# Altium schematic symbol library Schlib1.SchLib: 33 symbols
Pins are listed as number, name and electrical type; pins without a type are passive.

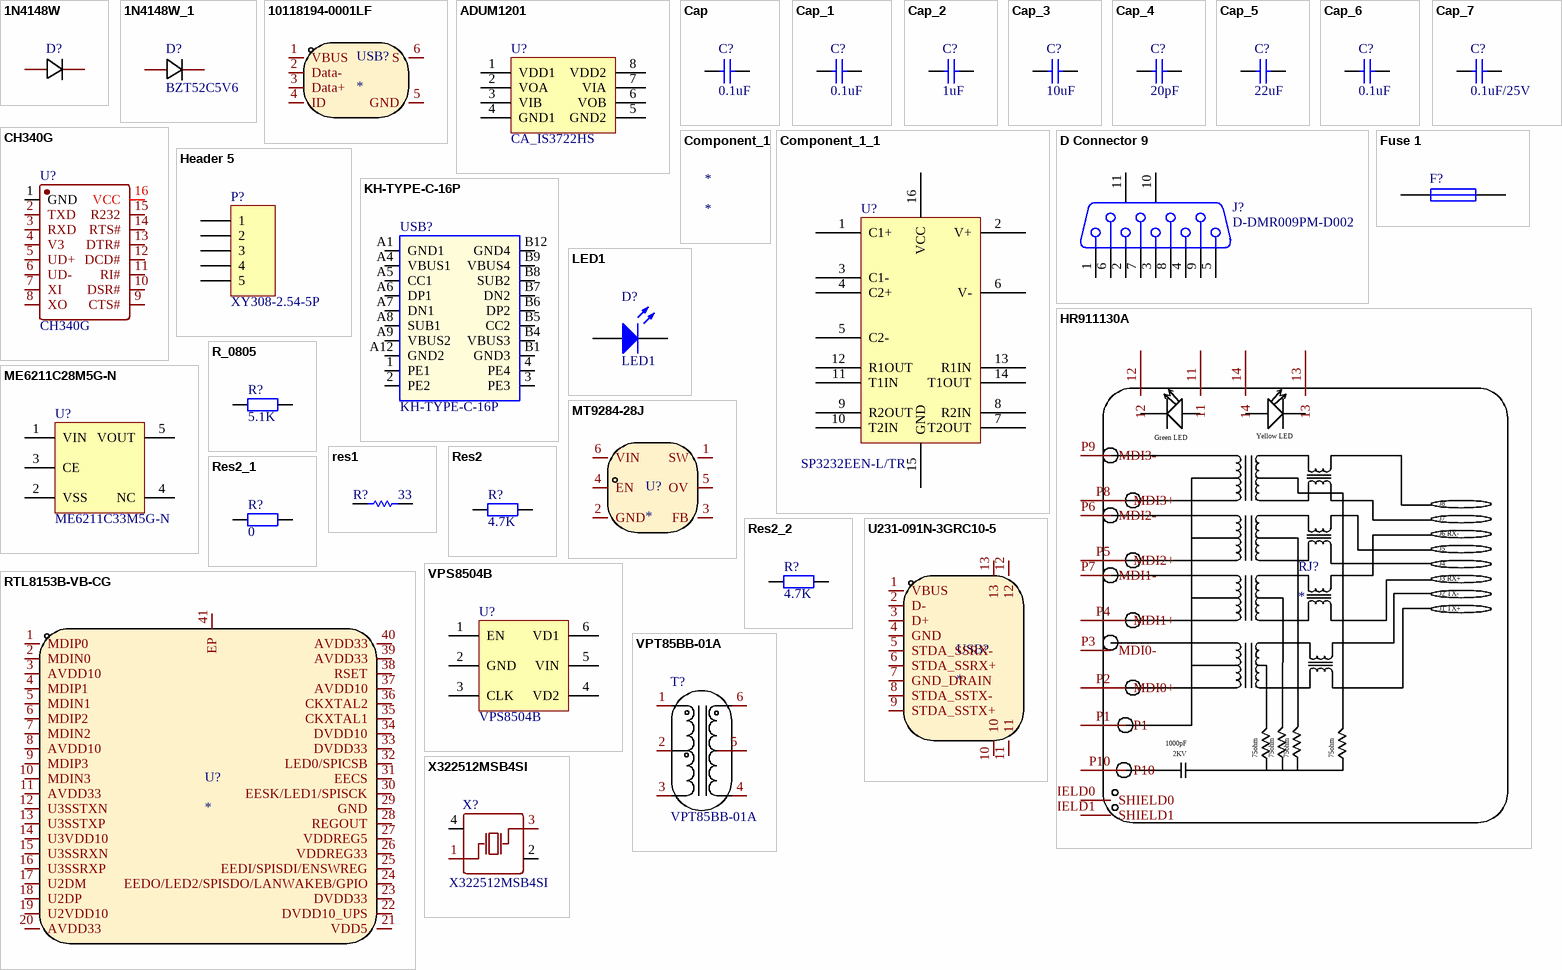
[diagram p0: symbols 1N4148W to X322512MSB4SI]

## 1N4148W
designator D?, comment B5819W SL  (value not drawn)
footprint SOD-123
pins: 1 C, 2 A

## 1N4148W_1
designator D?, comment BZT52C5V6
footprint SOD-123
pins: 1 C, 2 A

## 10118194-0001LF
designator USB?
pins: 1 VBUS, 2 Data-, 3 Data+, 4 ID, 5 GND, 6 S

## ADUM1201
designator U?, comment CA_IS3722HS
footprint SOP8
footprint SOP-8_150mil
pins: 1 VDD1, 2 VOA, 3 VIB, 4 GND1, 5 GND2, 6 VOB, 7 VIA, 8 VDD2

## Cap
designator C?, comment 0.1uF
贴片电容
footprint RAD-0.3 (Radial Cap, Thru-Hole; 2 Leads; 0.3 in Pin Spacing)
simulation model CAP (Capacitor)
signal-integrity model Cap
footprint 0805-C
footprint 0603-C
pins: 1, 2

## Cap_1
designator C?, comment 0.1uF
贴片电容
simulation model CAP (Capacitor)
signal-integrity model Cap
footprint 0603-C
pins: 1, 2

## Cap_2
designator C?, comment 1uF
贴片电容; Value: 0.1uF
footprint RAD-0.3 (Radial Cap, Thru-Hole; 2 Leads; 0.3 in Pin Spacing)
simulation model CAP (Capacitor)
signal-integrity model Cap
footprint 0805-C
footprint 0603-C
pins: 1, 2

## Cap_3
designator C?, comment 10uF
贴片电容; Value: 0.1uF
footprint RAD-0.3 (Radial Cap, Thru-Hole; 2 Leads; 0.3 in Pin Spacing)
simulation model CAP (Capacitor)
signal-integrity model Cap
footprint 0805-C
footprint 0603-C
footprint 0805-C
pins: 1, 2

## Cap_4
designator C?, comment 20pF
贴片电容
simulation model CAP (Capacitor)
signal-integrity model Cap
footprint 0603-C
pins: 1, 2

## Cap_5
designator C?, comment 22uF
贴片电容
simulation model CAP (Capacitor)
signal-integrity model Cap
footprint 0603-C
footprint 0805-C
pins: 1, 2

## Cap_6
designator C?, comment 0.1uF
Capacitor; Value: 100pF
footprint 0603C
footprint 0603-C
pins: 1, 2

## Cap_7
designator C?, comment 0.1uF/25V
贴片电容
simulation model CAP (Capacitor)
signal-integrity model Cap
footprint 0603-C
pins: 1, 2

## CH340G
designator U?
footprint SOP-16
pins: 1 GND, 2 TXD, 3 RXD, 4 V3, 5 UD+, 6 UD-, 7 XI, 8 XO, 9 CTS#, 10 DSR#, 11 RI#, 12 DCD#, 13 DTR#, 14 RTS#, 15 R232, 16 VCC

## Component_1
designator *

## Component_1_1
designator U?, comment SP3232EEN-L/TR
RS232电平转换芯片
footprint SOIC127P600-16L
pins: 1 C1+, 2 V+, 3 C1-, 4 C2+, 5 C2-, 6 V-, 7 T2OUT, 8 R2IN, 9 R2OUT, 10 T2IN, 11 T1IN, 12 R1OUT, 13 R1IN, 14 T1OUT, 15 GND, 16 VCC

## D Connector 9
designator J?, comment D-DMR009PM-D002
DB9连接器 母头; PackageDocument: O; Positions: 9; Gender: Receptacle
footprint DSUB1.385-2H9 (Connector; D Subminiature; 9 Position; Right Angle; Pitch 1.385 mm)
signal-integrity model Connector
pins: 1, 2, 3, 4, 5, 6, 7, 8, 9, 10 MH1, 11 MH2

## Fuse 1
designator F?, comment BSMD0805-050-24V  (value not drawn)
footprint PIN-W2/E2.8 (Thru-Hole; 2 Leads)
simulation model FUSE (Spice Subcircuit)
footprint 1206-F
footprint 0805-L
pins: 1, 2

## Header 5
designator P?, comment XY308-2.54-5P
Header, 5-Pin
footprint HDR1X5 (Connector; Header; 5 Position)
signal-integrity model Connector
footprint CONN-TH_XY308-2.54-5P (2.54接线端子)
footprint Model Name (Footprint not found)
footprint CONN-TH_5P-P3.81_KF124-3.81-5P (3.81 5P接线端子)
pins: 1, 2, 3, 4, 5

## HR911130A
designator RJ?
pins: 11, 12, 13, 14, P1, P2 MDI0+, P3 MDI0-, P4 MDI1+, P5 MDI2+, P6 MDI2-, P7 MDI1-, P8 MDI3+, P9 MDI3-, P10, SHIELD0, SHIELD1

## KH-TYPE-C-16P
designator USB?
Type-C
footprint USB-C-SMD_KH-TYPE-C-16P
pins: 1 PE1, 2 PE2, 3 PE3, 4 PE4, A1 GND1, A4 VBUS1, A5 CC1, A6 DP1, A7 DN1, A8 SUB1, A9 VBUS2, A12 GND2, B1 GND3, B4 VBUS3, B5 CC2, B6 DP2, B7 DN2, B8 SUB2, B9 VBUS4, B12 GND4

## LED1
designator D?
LED-绿
footprint LED-1 (LED; 2 Leads)
simulation model LED1 (Diode)
footprint 0805-LED
footprint 0603-LED
footprint LED-TH_BD3.0-P2.54
pins: 1 A, 2 K

## ME6211C28M5G-N
designator U?, comment ME6211C33M5G-N
LDO-2.8V
footprint SOT-23-5
pins: 1 VIN, 2 VSS, 3 CE, 4 NC, 5 VOUT

## MT9284-28J
designator U?
pins: 1 SW, 2 GND, 3 FB, 4 EN, 5 OV, 6 VIN

## R_0805
designator R?, comment 5.1K
电阻
footprint 0603- R
pins: 1, 2

## res1
designator R?, comment 33
Resistor; Value: 1K
simulation model RESISTOR (Resistor)
signal-integrity model Res
footprint R0603
footprint 0603- R
pins: 1, 2
1 alternate drawing of the same symbol

## Res2
designator R?, comment 4.7K
贴片电阻
footprint AXIAL-0.4 (Axial Device, Thru-Hole; 2 Leads; 0.4 in Pin Spacing)
simulation model RESISTOR (Resistor)
signal-integrity model Res
footprint 0805-R
footprint 0603- R
pins: 1, 2

## Res2_1
designator R?, comment 0
贴片电阻
simulation model RESISTOR (Resistor)
signal-integrity model Res
footprint 0603- R
pins: 1, 2

## Res2_2
designator R?, comment 4.7K
贴片电阻
simulation model RESISTOR (Resistor)
signal-integrity model Res
footprint 0603- R
pins: 1, 2

## RTL8153B-VB-CG
designator U?
footprint QFN-40-EP(5x5)
pins: 1 MDIP0, 2 MDIN0, 3 AVDD10, 4 MDIP1, 5 MDIN1, 6 MDIP2, 7 MDIN2, 8 AVDD10, 9 MDIP3, 10 MDIN3, 11 AVDD33, 12 U3SSTXN, 13 U3SSTXP, 14 U3VDD10, 15 U3SSRXN, 16 U3SSRXP, 17 U2DM, 18 U2DP, 19 U2VDD10, 20 AVDD33, 21 VDD5, 22 DVDD10_UPS, 23 DVDD33, 24 EEDO/LED2/SPISDO/LANWAKEB/GPIO, 25 EEDI/SPISDI/ENSWREG, 26 VDDREG33, 27 VDDREG5, 28 REGOUT, 29 GND, 30 EESK/LED1/SPISCK, 31 EECS, 32 LED0/SPICSB, 33 DVDD33, 34 DVDD10, 35 CKXTAL1, 36 CKXTAL2, 37 AVDD10, 38 RSET, 39 AVDD33, 40 AVDD33, 41 EP

## U231-091N-3GRC10-5
designator USB?
USB3.0
footprint USB-A-TH_U231-091N-5
pins: 1 VBUS, 2 D-, 3 D+, 4 GND, 5 STDA_SSRX-, 6 STDA_SSRX+, 7 GND_DRAIN, 8 STDA_SSTX-, 9 STDA_SSTX+, 10, 11, 12, 13

## VPS8504B
designator U?
footprint SOT-23-6 (LED驱动-LM3519)
pins: 1 EN , 2 GND, 3 CLK, 4 VD2, 5 VIN, 6 VD1

## VPT85BB-01A
designator T?
变压器
footprint VPT85BB-01A
pins: 1, 2, 3, 4, 5, 6

## X322512MSB4SI
designator X?
4脚无源晶振
footprint OSC-SMD_4P-L3.2-W2.5-BL (晶振27M-3225)
pins: 1 OSC1, 2 GND, 3 OSC2, 4 GND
